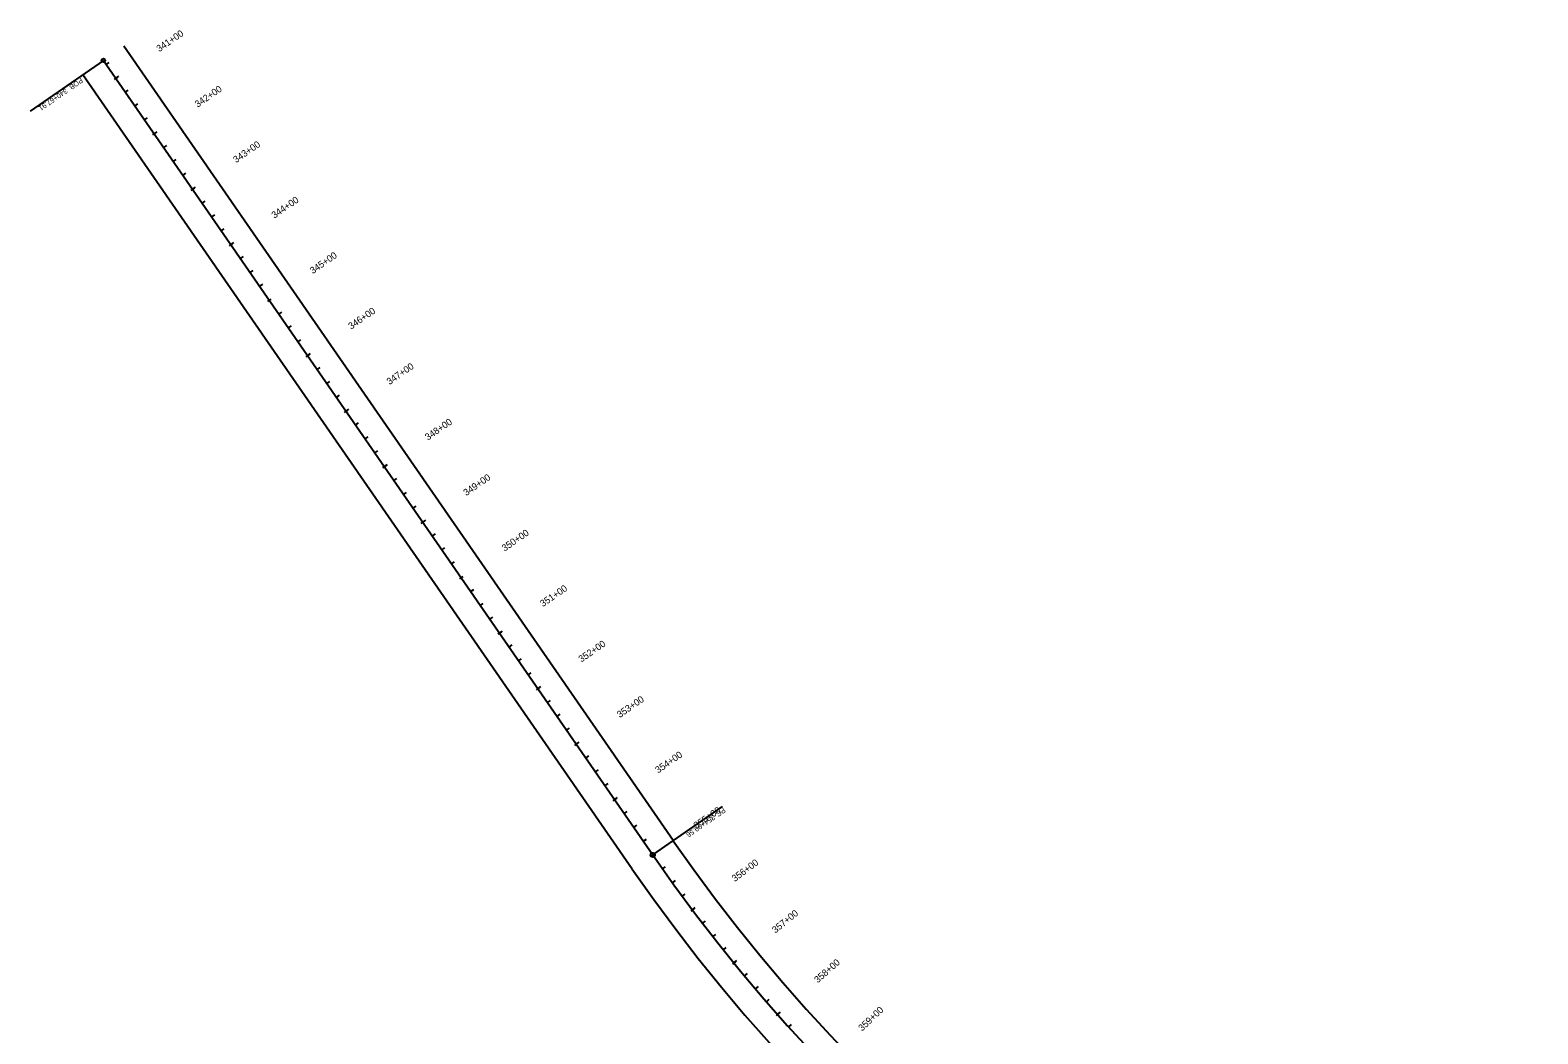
# Model space of a CAD drawing. Extents: x 21369364 to 21378321, y 8396964 to 8399934.
# Drawn here: x 21369364 to 21371598, y 8398446 to 8399934 of the extents above; entities that cross this region are included whole.
import ezdxf

# ---------------------------------------------------------------- set-up
doc = ezdxf.new("R2010")
doc.units = 0
for name, color, linetype in [('Alignment', 7, 'Continuous'), ('Level 1', 7, 'Continuous'), ('Level 60', 7, 'Continuous'), ('TextNonPlot', 7, 'Continuous')]:
    doc.layers.add(name, color=color, linetype=linetype)

msp = doc.modelspace()

# ---------------------------------------------------------------- linework, layer by layer
at = {"layer": 'Alignment'}
msp.add_line((21369472.4, 8399889), (21370286.5, 8398711.3), dxfattribs=at)
msp.add_arc((21372381.2, 8400159.4), 2546.5, 214.6562, 290.16, dxfattribs=at)
at = {"layer": 'Level 1'}
for p, q in [((21369472.4, 8399889), (21369363.8, 8399813.9)), ((21369363.8, 8399813.9), (21369363.8, 8399813.9)), ((21370286.5, 8398711.3), (21370390.1, 8398783)), ((21370390.1, 8398783), (21370390.1, 8398783))]:
    msp.add_line(p, q, dxfattribs=at)
for centre, radius in [((21369472.4, 8399889), 2.67), ((21370286.5, 8398711.3), 3.12)]:
    msp.add_circle(centre, radius, dxfattribs=at)
at = {"layer": 'Level 60'}
for p, q in [((21369476.4, 8399883.1), (21369480.9, 8399886.2)), ((21369493.2, 8399864.3), (21369488.1, 8399860.8)), ((21369504.9, 8399842), (21369509.3, 8399845.1)), ((21369519.1, 8399821.4), (21369523.6, 8399824.6)), ((21369533.3, 8399800.9), (21369537.8, 8399804)), ((21369550, 8399782.1), (21369545, 8399778.6)), ((21369561.7, 8399759.8), (21369566.2, 8399762.9)), ((21369575.9, 8399739.2), (21369580.4, 8399742.3)), ((21369590.2, 8399718.6), (21369594.6, 8399721.7)), ((21369606.9, 8399699.8), (21369601.9, 8399696.3)), ((21369618.6, 8399677.5), (21369623.1, 8399680.6)), ((21369632.8, 8399656.9), (21369637.3, 8399660)), ((21369647, 8399636.4), (21369651.5, 8399639.5)), ((21369663.8, 8399617.5), (21369658.7, 8399614.1)), ((21369675.5, 8399595.2), (21369679.9, 8399598.3)), ((21369689.7, 8399574.7), (21369694.2, 8399577.8)), ((21369703.9, 8399554.1), (21369708.4, 8399557.2)), ((21369720.6, 8399535.3), (21369715.6, 8399531.8)), ((21369732.3, 8399513), (21369736.8, 8399516.1)), ((21369746.5, 8399492.4), (21369751, 8399495.5)), ((21369760.7, 8399471.9), (21369765.2, 8399475)), ((21369777.5, 8399453), (21369772.4, 8399449.5)), ((21369789.2, 8399430.7), (21369793.7, 8399433.8)), ((21369803.4, 8399410.2), (21369807.9, 8399413.3)), ((21369817.6, 8399389.6), (21369822.1, 8399392.7)), ((21369834.3, 8399370.8), (21369829.3, 8399367.3)), ((21369846, 8399348.5), (21369850.5, 8399351.6)), ((21369860.3, 8399327.9), (21369864.8, 8399331)), ((21369874.5, 8399307.3), (21369879, 8399310.4)), ((21369891.2, 8399288.5), (21369886.2, 8399285)), ((21369902.9, 8399266.2), (21369907.4, 8399269.3)), ((21369917.1, 8399245.6), (21369921.6, 8399248.7)), ((21369931.3, 8399225.1), (21369935.8, 8399228.2)), ((21369948.1, 8399206.3), (21369943, 8399202.8)), ((21369959.8, 8399184), (21369964.3, 8399187.1)), ((21369974, 8399163.4), (21369978.5, 8399166.5)), ((21369988.2, 8399142.8), (21369992.7, 8399145.9)), ((21370004.9, 8399124), (21369999.9, 8399120.5)), ((21370016.6, 8399101.7), (21370021.1, 8399104.8)), ((21370030.9, 8399081.1), (21370035.3, 8399084.2)), ((21370045.1, 8399060.6), (21370049.6, 8399063.7)), ((21370061.8, 8399041.7), (21370056.8, 8399038.3)), ((21370073.5, 8399019.4), (21370078, 8399022.5)), ((21370087.7, 8398998.9), (21370092.2, 8399002)), ((21370101.9, 8398978.3), (21370106.4, 8398981.4)), ((21370118.7, 8398959.5), (21370113.6, 8398956)), ((21370130.4, 8398937.2), (21370134.9, 8398940.3)), ((21370144.6, 8398916.6), (21370149.1, 8398919.7)), ((21370158.8, 8398896), (21370163.3, 8398899.2)), ((21370175.5, 8398877.2), (21370170.5, 8398873.7)), ((21370187.2, 8398854.9), (21370191.7, 8398858)), ((21370201.5, 8398834.4), (21370205.9, 8398837.5)), ((21370215.7, 8398813.8), (21370220.2, 8398816.9)), ((21370232.4, 8398795), (21370227.4, 8398791.5)), ((21370244.1, 8398772.7), (21370248.6, 8398775.8)), ((21370258.3, 8398752.1), (21370262.8, 8398755.2)), ((21370272.5, 8398731.5), (21370277, 8398734.6)), ((21370289.3, 8398712.7), (21370284.2, 8398709.2)), ((21370301.1, 8398690.5), (21370305.5, 8398693.6)), ((21370315.6, 8398670.1), (21370320, 8398673.3)), ((21370330.3, 8398649.9), (21370334.7, 8398653.2)), ((21370347.7, 8398631.7), (21370342.8, 8398628)), ((21370360.3, 8398609.9), (21370364.7, 8398613.3)), ((21370375.7, 8398590.2), (21370380, 8398593.5)), ((21370391.2, 8398570.6), (21370395.4, 8398574)), ((21370409.2, 8398553), (21370404.5, 8398549.2)), ((21370422.7, 8398531.8), (21370426.9, 8398535.3)), ((21370438.8, 8398512.7), (21370443, 8398516.2)), ((21370455.1, 8398493.7), (21370459.2, 8398497.2)), ((21370473.8, 8398476.9), (21370469.2, 8398472.8)), ((21370488.1, 8398456.2), (21370492.2, 8398459.8))]:
    msp.add_line(p, q, dxfattribs=at)
at = {"layer": 'TextNonPlot'}
for p, q in [((21370316.9, 8398732.4), (21369502.8, 8399910)), ((21370256.1, 8398690.3), (21369442, 8399867.9)), ((21369490.6, 8399862.6), (21369495.1, 8399865.7)), ((21369547.5, 8399780.3), (21369552, 8399783.4)), ((21369604.4, 8399698.1), (21369608.9, 8399701.2)), ((21369661.2, 8399615.8), (21369665.7, 8399618.9)), ((21369720.6, 8399535.3), (21369715.6, 8399531.8)), ((21369775, 8399451.3), (21369779.5, 8399454.4)), ((21369831.8, 8399369), (21369836.3, 8399372.1)), ((21369888.7, 8399286.8), (21369893.2, 8399289.9)), ((21369945.6, 8399204.5), (21369950.1, 8399207.6)), ((21370004.9, 8399124), (21369999.9, 8399120.5)), ((21370059.3, 8399040), (21370063.8, 8399043.1)), ((21370116.2, 8398957.7), (21370120.6, 8398960.8)), ((21370173, 8398875.5), (21370177.5, 8398878.6)), ((21370229.9, 8398793.2), (21370234.4, 8398796.3)), ((21370289.3, 8398712.7), (21370284.2, 8398709.2)), ((21370345.2, 8398629.9), (21370349.6, 8398633.1)), ((21370406.8, 8398551.1), (21370411.1, 8398554.6)), ((21370471.5, 8398474.8), (21370475.6, 8398478.4))]:
    msp.add_line(p, q, dxfattribs=at)
for radius in [2509.5, 2583.5]:
    msp.add_arc((21372381.2, 8400159.4), radius, 214.6562, 290.16, dxfattribs=at)

# ---------------------------------------------------------------- texts
at = {"layer": 'Level 1'}
for s, p in [('POB ', (21369438.8, 8399863.7)), ('340+67.91', (21369416, 8399848)), ('PC', (21370391.1, 8398781.6)), ('354+99.56', (21370375.7, 8398771))]:
    msp.add_text(s, height=7.5, rotation=214.6562, dxfattribs=at).set_placement(p)
at = {"layer": 'Level 60'}
for s, rotation, p in [('341+00', 34.6562, (21369555.2, 8399901.1)), ('342+00', 34.6562, (21369612, 8399818.8)), ('343+00', 34.6562, (21369668.9, 8399736.6)), ('344+00', 34.6562, (21369725.8, 8399654.3)), ('345+00', 34.6562, (21369782.6, 8399572.1)), ('346+00', 34.6562, (21369839.5, 8399489.8)), ('347+00', 34.6562, (21369896.4, 8399407.6)), ('348+00', 34.6562, (21369953.2, 8399325.3)), ('349+00', 34.6562, (21370010.1, 8399243)), ('350+00', 34.6562, (21370067, 8399160.8)), ('351+00', 34.6562, (21370123.8, 8399078.5)), ('352+00', 34.6562, (21370180.7, 8398996.3)), ('353+00', 34.6562, (21370237.6, 8398914)), ('354+00', 34.6562, (21370294.4, 8398831.8)), ('355+00', 34.666, (21370351.3, 8398749.5)), ('356+00', 36.916, (21370408.2, 8398670.9)), ('357+00', 39.166, (21370468.2, 8398594.6)), ('358+00', 41.416, (21370531.1, 8398520.7)), ('359+00', 43.666, (21370596.8, 8398449.3))]:
    msp.add_text(s, height=10.02, rotation=rotation, dxfattribs=at).set_placement(p)
at = {"layer": 'TextNonPlot'}
for s, rotation, p in [('345+00', 34.6562, (21369782.6, 8399572.1)), ('350+00', 34.6562, (21370067, 8399160.8)), ('355+00', 34.666, (21370351.3, 8398749.5))]:
    msp.add_text(s, height=10.02, rotation=rotation, dxfattribs=at).set_placement(p)

doc.saveas('drawing.dxf')
